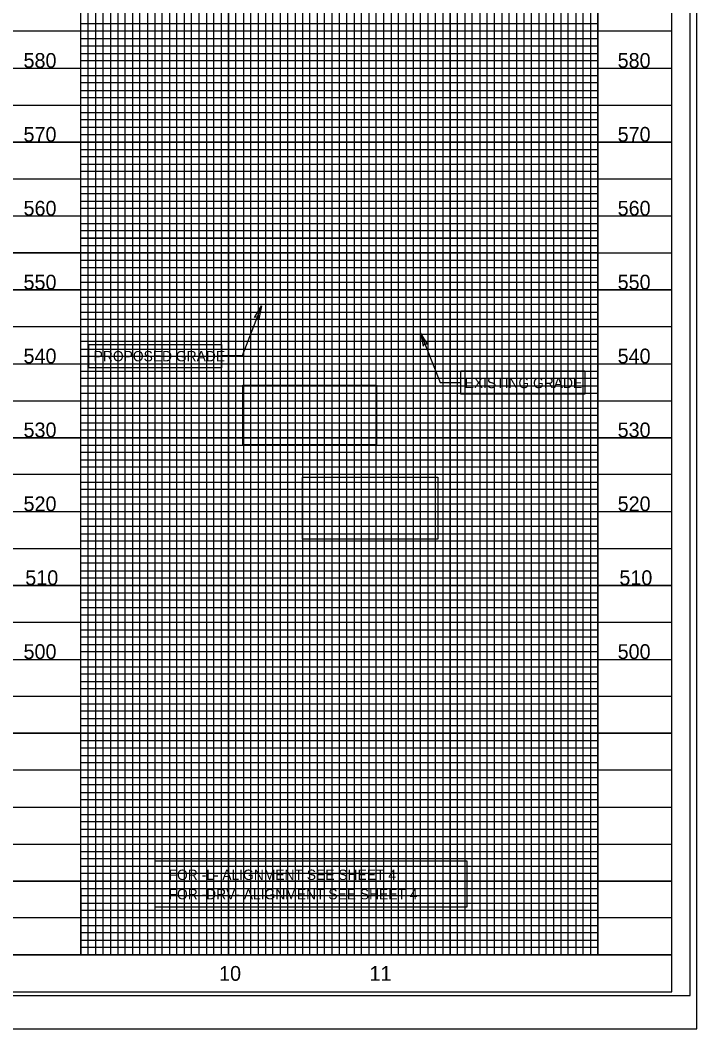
# Model space of a CAD drawing. Extents: x 1735444 to 1737729, y 696688 to 698970.
# Drawn here: x 1737271 to 1737729, y 697635 to 698318 of the extents above; entities that cross this region are included whole.
import ezdxf

# ---------------------------------------------------------------- set-up
doc = ezdxf.new("R2010")
doc.units = 0
for name, color, linetype in [('Exist Vertical Profile Horizontal Axis Label Major', 7, 'Continuous'), ('Exist Vertical Profile Vertical Axis Label', 7, 'Continuous'), ('Prop Grid Mask', 7, 'Continuous'), ('Prop PFL Text', 7, 'Continuous'), ('Prop Terminator CELL', 7, 'Continuous'), ('Prop VPI Label', 7, 'Continuous'), ('Sheet Cutting Line CELL', 7, 'Continuous'), ('Sheet DOT Grid CELL', 7, 'Continuous'), ('Sheet Layout Profile Border', 7, 'Continuous'), ('Sheet Plot Border Inside CELL', 7, 'Continuous'), ('Sheet Plot Border Outside CELL', 7, 'Continuous'), ('Sheet Profile CELL', 7, 'Continuous'), ('Sheet Profile Grid Major CELL', 7, 'Continuous'), ('Sheet Profile Grid Middle CELL', 7, 'Continuous'), ('Sheet Profile Grid Minor CELL', 7, 'Continuous')]:
    doc.layers.add(name, color=color, linetype=linetype)

msp = doc.modelspace()

# ---------------------------------------------------------------- linework, layer by layer
at = {"layer": 'Prop Grid Mask'}
for points in [[(1737317.56, 698098.19), (1737407.19, 698098.19), (1737407.19, 698082.43), (1737317.56, 698082.43)], [(1737569.28, 698080.28), (1737653.32, 698080.28), (1737653.32, 698064.52), (1737569.28, 698064.52)], [(1737421.76, 698070.57), (1737512.15, 698070.57), (1737512.15, 698030.37), (1737421.76, 698030.37)], [(1737462.19, 698008.39), (1737553.64, 698008.39), (1737553.64, 697966.39), (1737462.19, 697966.39)], [(1737573.49, 697748.56), (1737362.07, 697748.56), (1737362.07, 697717.68), (1737573.49, 697717.68)]]:
    msp.add_lwpolyline(points, close=True, dxfattribs=at)
at = {"layer": 'Prop Terminator CELL'}
for points in [[(1737429.69, 698116.5), (1737434.41, 698124.31), (1737432.6, 698115.3), (1737431.53, 698116.96)], [(1737546.78, 698098.36), (1737542.05, 698106.17), (1737543.86, 698097.16), (1737544.93, 698098.82)]]:
    msp.add_lwpolyline(points, close=True, dxfattribs=at)
at = {"layer": 'Prop VPI Label'}
for p, q in [((1737434.41, 698124.31), (1737421.19, 698090.55)), ((1737542.05, 698106.17), (1737555.28, 698072.4)), ((1737421.19, 698090.55), (1737407.19, 698090.55)), ((1737555.28, 698072.4), (1737569.28, 698072.4))]:
    msp.add_line(p, q, dxfattribs=at)
at = {"layer": 'Sheet Cutting Line CELL'}
msp.add_line((1736045.07, 697635.13), (1737729.07, 697635.13), dxfattribs=at)
at = {"layer": 'Sheet DOT Grid CELL'}
for p, q in [((1737362.07, 698710.13), (1737362.07, 697685.13)), ((1737412.07, 698617.69), (1737412.07, 697685.13)), ((1737462.07, 698617.69), (1737462.07, 697685.13)), ((1737512.07, 697685.13), (1737512.07, 698572.58)), ((1737562.07, 697685.13), (1737562.07, 698572.58)), ((1737612.07, 697685.13), (1737612.07, 698572.58)), ((1737662.07, 697685.13), (1737662.07, 698572.58)), ((1736212.07, 698285.13), (1737712.07, 698285.13)), ((1736212.07, 698235.13), (1737712.07, 698235.13)), ((1736212.07, 698185.13), (1737712.07, 698185.13)), ((1736212.07, 698135.13), (1737712.07, 698135.13)), ((1736212.07, 698085.13), (1737712.07, 698085.13)), ((1736212.07, 698035.13), (1737712.07, 698035.13)), ((1736212.07, 697985.13), (1737712.07, 697985.13)), ((1736212.07, 697935.13), (1737712.07, 697935.13)), ((1736212.07, 697885.13), (1737274.3, 697885.13)), ((1737274.3, 697885.13), (1737712.07, 697885.13)), ((1736212.07, 697835.13), (1737274.9, 697835.13)), ((1737274.9, 697835.13), (1737712.07, 697835.13)), ((1736212.07, 697785.13), (1737274.3, 697785.13)), ((1737274.3, 697785.13), (1737712.07, 697785.13)), ((1736212.07, 697735.13), (1737274.3, 697735.13)), ((1737274.3, 697735.13), (1737712.07, 697735.13)), ((1737312.07, 697730.13), (1737312.07, 697685.13))]:
    msp.add_line(p, q, dxfattribs=at)
at = {"layer": 'Sheet Layout Profile Border'}
msp.add_lwpolyline([(1737512.02, 698661.7), (1737512.02, 698710.13), (1736262.07, 698710.13), (1736262.07, 697685.13), (1737662.07, 697685.13), (1737662.07, 698572.58), (1737512.02, 698572.58), (1737512.02, 698617.69)], dxfattribs=at)
at = {"layer": 'Sheet Plot Border Inside CELL'}
msp.add_lwpolyline([(1737724.57, 698712.68), (1736058.07, 698712.68), (1736058.07, 697657.58), (1737724.57, 697657.58)], close=True, dxfattribs=at)
at = {"layer": 'Sheet Plot Border Outside CELL'}
msp.add_lwpolyline([(1737729.07, 698735.13), (1736045.07, 698735.13), (1736045.07, 697635.13), (1737729.07, 697635.13)], close=True, dxfattribs=at)
at = {"layer": 'Sheet Profile CELL'}
msp.add_line((1737712.07, 697685.13), (1736212.07, 697685.13), dxfattribs=at)
msp.add_lwpolyline([(1737712.07, 698710.13), (1736212.07, 698710.13), (1736212.07, 697660.13), (1737712.07, 697660.13)], close=True, dxfattribs=at)
at = {"layer": 'Sheet Profile Grid Major CELL'}
for points in [[(1736962.07, 697685.13), (1737012.07, 697685.13), (1737012.07, 698710.13), (1737062.07, 698710.13), (1737062.07, 697685.13), (1737112.07, 697685.13), (1737112.07, 698710.13), (1737162.07, 698710.13), (1737162.07, 697685.13), (1737212.07, 697685.13), (1737212.07, 698710.13), (1737262.07, 698710.13), (1737262.07, 697685.13), (1737312.07, 697685.13), (1737312.07, 698710.13), (1737362.07, 698710.13), (1737362.07, 697685.13), (1737412.07, 697685.13), (1737412.07, 698617.69)], [(1737462.07, 698617.69), (1737462.07, 697685.13), (1737512.07, 697685.13), (1737512.07, 698710.13), (1737538.37, 698710.13)], [(1737562.07, 698572.58), (1737562.07, 697685.13), (1737612.07, 697685.13), (1737612.07, 698572.58)], [(1737662.07, 698572.58), (1737662.07, 697685.13), (1737712.07, 697685.13)], [(1737712.07, 698235.13), (1736212.07, 698235.13), (1736212.07, 698285.13), (1737712.07, 698285.13)], [(1737712.07, 698135.13), (1736212.07, 698135.13), (1736212.07, 698185.13), (1737712.07, 698185.13)], [(1737712.07, 698035.13), (1736212.07, 698035.13), (1736212.07, 698085.13), (1737712.07, 698085.13)], [(1737712.07, 697935.13), (1736212.07, 697935.13), (1736212.07, 697985.13), (1737712.07, 697985.13)], [(1737712.07, 697835.13), (1736212.07, 697835.13), (1736212.07, 697885.13), (1737712.07, 697885.13)], [(1737712.07, 697735.13), (1736212.07, 697735.13), (1736212.07, 697785.13), (1737712.07, 697785.13)]]:
    msp.add_lwpolyline(points, dxfattribs=at)
at = {"layer": 'Sheet Profile Grid Middle CELL'}
for points in [[(1737312.07, 698710.13), (1737312.07, 698710.13), (1737337.07, 698710.13), (1737337.07, 697685.13), (1737387.07, 697685.13), (1737387.07, 698617.69)], [(1737437.07, 698617.69), (1737437.07, 697685.13), (1737487.07, 697685.13), (1737487.07, 698617.69)], [(1737537.07, 698572.58), (1737537.07, 697685.13), (1737587.07, 697685.13), (1737587.07, 698572.58)], [(1737637.07, 698572.58), (1737637.07, 697685.13)], [(1737712.07, 698310.13), (1736212.07, 698310.13), (1736212.07, 698260.13), (1737712.07, 698260.13)], [(1737712.07, 698210.13), (1736212.07, 698210.13), (1736212.07, 698160.13), (1737712.07, 698160.13)], [(1737712.07, 698110.13), (1736212.07, 698110.13), (1736212.07, 698060.13), (1737712.07, 698060.13)], [(1737712.07, 698010.13), (1736212.07, 698010.13), (1736212.07, 697960.13), (1737712.07, 697960.13)], [(1737275.01, 697910.13), (1736212.07, 697910.13), (1736212.07, 697860.13), (1737274.3, 697860.13)], [(1737712.07, 697910.13), (1737275.01, 697910.13)], [(1737274.3, 697860.13), (1737712.07, 697860.13)], [(1737274.9, 697810.13), (1736212.07, 697810.13), (1736212.07, 697760.13), (1737274.01, 697760.13)], [(1737712.07, 697810.13), (1737274.9, 697810.13)], [(1737274.01, 697760.13), (1737712.07, 697760.13)], [(1737712.07, 697710.13), (1736212.07, 697710.13)]]:
    msp.add_lwpolyline(points, dxfattribs=at)
at = {"layer": 'Sheet Profile Grid Minor CELL'}
for points in [[(1737307.07, 697685.13), (1737317.07, 697685.13), (1737317.07, 698710.13)], [(1737322.07, 698710.13), (1737322.07, 697685.13), (1737327.07, 697685.13), (1737327.07, 698710.13)], [(1737332.07, 698710.13), (1737332.07, 697685.13), (1737342.07, 697685.13), (1737342.07, 698710.13)], [(1737347.07, 698710.13), (1737347.07, 697685.13), (1737352.07, 697685.13), (1737352.07, 698710.13)], [(1737357.07, 698710.13), (1737357.07, 697685.13), (1737367.07, 697685.13), (1737367.07, 698710.13)], [(1737372.07, 698710.13), (1737372.07, 697685.13), (1737377.07, 697685.13), (1737377.07, 698710.13)], [(1737382.07, 698617.69), (1737382.07, 697685.13), (1737392.07, 697685.13), (1737392.07, 698617.69)], [(1737397.07, 698617.69), (1737397.07, 697685.13), (1737402.07, 697685.13), (1737402.07, 698617.69)], [(1737407.07, 698617.69), (1737407.07, 697685.13), (1737417.07, 697685.13), (1737417.07, 698617.69)], [(1737422.07, 698617.69), (1737422.07, 697685.13), (1737427.07, 697685.13), (1737427.07, 698617.69)], [(1737432.07, 698617.69), (1737432.07, 697685.13), (1737442.07, 697685.13), (1737442.07, 698617.69)], [(1737447.07, 698617.69), (1737447.07, 697685.13), (1737452.07, 697685.13), (1737452.07, 698617.69)], [(1737457.07, 698617.69), (1737457.07, 697685.13), (1737467.07, 697685.13), (1737467.07, 698617.69)], [(1737472.07, 698617.69), (1737472.07, 697685.13), (1737477.07, 697685.13), (1737477.07, 698617.69)], [(1737482.07, 698617.69), (1737482.07, 697685.13), (1737492.07, 697685.13), (1737492.07, 698617.69)], [(1737497.07, 698617.69), (1737497.07, 697685.13), (1737502.07, 697685.13), (1737502.07, 698617.69)], [(1737507.07, 698617.69), (1737507.07, 697685.13), (1737517.07, 697685.13), (1737517.07, 698572.58)], [(1737522.07, 698572.58), (1737522.07, 697685.13), (1737527.07, 697685.13), (1737527.07, 698572.58)], [(1737532.07, 698572.58), (1737532.07, 697685.13), (1737542.07, 697685.13), (1737542.07, 698572.58)], [(1737547.07, 698572.58), (1737547.07, 697685.13), (1737552.07, 697685.13), (1737552.07, 698572.58)], [(1737557.07, 698572.58), (1737557.07, 697685.13), (1737567.07, 697685.13), (1737567.07, 698572.58)], [(1737572.07, 698572.58), (1737572.07, 697685.13), (1737577.07, 697685.13), (1737577.07, 698572.58)], [(1737582.07, 698572.58), (1737582.07, 697685.13), (1737592.07, 697685.13), (1737592.07, 698572.58)], [(1737597.07, 698572.58), (1737597.07, 697685.13)], [(1737597.07, 697685.13), (1737602.07, 697685.13), (1737602.07, 698572.58)], [(1737607.07, 698572.58), (1737607.07, 697685.13), (1737617.07, 697685.13), (1737617.07, 698572.58)], [(1737622.07, 698572.58), (1737622.07, 697685.13), (1737627.07, 697685.13), (1737627.07, 698572.58)], [(1737632.07, 698572.58), (1737632.07, 697685.13), (1737642.07, 697685.13), (1737642.07, 698572.58)], [(1737647.07, 698572.58), (1737647.07, 697685.13), (1737652.07, 697685.13), (1737652.07, 698572.58)], [(1737657.07, 698572.58), (1737657.07, 697685.13), (1737667.07, 697685.13)], [(1737662.07, 698315.13), (1737312.07, 698315.13)], [(1737312.07, 698305.13), (1737662.07, 698305.13)], [(1737662.07, 698300.13), (1737312.07, 698300.13)], [(1737312.07, 698295.13), (1737662.07, 698295.13)], [(1737662.07, 698290.13), (1737312.07, 698290.13)], [(1737312.07, 698280.13), (1737662.07, 698280.13)], [(1737662.07, 698275.13), (1737312.07, 698275.13)], [(1737312.07, 698270.13), (1737662.07, 698270.13)], [(1737662.07, 698265.13), (1737312.07, 698265.13)], [(1737312.07, 698255.13), (1737662.07, 698255.13)], [(1737662.07, 698250.13), (1737312.07, 698250.13)], [(1737312.07, 698245.13), (1737662.07, 698245.13)], [(1737662.07, 698240.13), (1737312.07, 698240.13)], [(1737312.07, 698230.13), (1737662.07, 698230.13)], [(1737662.07, 698225.13), (1737312.07, 698225.13)], [(1737312.07, 698220.13), (1737662.07, 698220.13)], [(1737662.07, 698215.13), (1737312.07, 698215.13)], [(1737312.07, 698205.13), (1737662.07, 698205.13)], [(1737662.07, 698200.13), (1737312.07, 698200.13)], [(1737312.07, 698195.13), (1737662.07, 698195.13)], [(1737662.07, 698190.13), (1737312.07, 698190.13)], [(1737312.07, 698180.13), (1737662.07, 698180.13)], [(1737662.07, 698175.13), (1737312.07, 698175.13)], [(1737312.07, 698170.13), (1737662.07, 698170.13)], [(1737662.07, 698170.13), (1737312.07, 698170.13)], [(1737312.07, 698165.13), (1737662.07, 698165.13)], [(1737662.07, 698160.13), (1736262.07, 698160.13), (1736262.07, 698155.13), (1737262.07, 698155.13)], [(1737312.07, 698155.13), (1737662.07, 698155.13)], [(1737662.07, 698150.13), (1737312.07, 698150.13)], [(1737312.07, 698145.13), (1737662.07, 698145.13)], [(1737662.07, 698140.13), (1737312.07, 698140.13)], [(1737312.07, 698130.13), (1737662.07, 698130.13)], [(1737662.07, 698125.13), (1737312.07, 698125.13)], [(1737312.07, 698120.13), (1737662.07, 698120.13)], [(1737662.07, 698115.13), (1737312.07, 698115.13)], [(1737312.07, 698105.13), (1737662.07, 698105.13)], [(1737662.07, 698100.13), (1737312.07, 698100.13)], [(1737312.07, 698095.13), (1737662.07, 698095.13)], [(1737662.07, 698090.13), (1737312.07, 698090.13)], [(1737312.07, 698080.13), (1737662.07, 698080.13)], [(1737662.07, 698075.13), (1737312.07, 698075.13)], [(1737312.07, 698070.13), (1737662.07, 698070.13)], [(1737662.07, 698065.13), (1737312.07, 698065.13)], [(1737312.07, 698055.13), (1737662.07, 698055.13)], [(1737662.07, 698050.13), (1737312.07, 698050.13)], [(1737312.07, 698045.13), (1737662.07, 698045.13)], [(1737662.07, 698040.13), (1737312.07, 698040.13)], [(1737312.07, 698030.13), (1737662.07, 698030.13)], [(1737662.07, 698025.13), (1737312.07, 698025.13)], [(1737312.07, 698020.13), (1737662.07, 698020.13)], [(1737662.07, 698015.13), (1737312.07, 698015.13)], [(1737312.07, 698005.13), (1737662.07, 698005.13)], [(1737662.07, 698000.13), (1737312.07, 698000.13)], [(1737312.07, 697995.13), (1737662.07, 697995.13)], [(1737662.07, 697990.13), (1737312.07, 697990.13)], [(1737312.07, 697980.13), (1737662.07, 697980.13)], [(1737662.07, 697975.13), (1737312.07, 697975.13)], [(1737312.07, 697970.13), (1737662.07, 697970.13)], [(1737662.07, 697965.13), (1737312.07, 697965.13)], [(1737312.07, 697955.13), (1737662.07, 697955.13)], [(1737662.07, 697950.13), (1737312.07, 697950.13)], [(1737312.07, 697945.13), (1737662.07, 697945.13)], [(1737662.07, 697940.13), (1737312.07, 697940.13)], [(1737312.07, 697930.13), (1737662.07, 697930.13)], [(1737662.07, 697925.13), (1737312.07, 697925.13)], [(1737312.07, 697920.13), (1737662.07, 697920.13)], [(1737662.07, 697915.13), (1737312.07, 697915.13)], [(1737312.07, 697905.13), (1737662.07, 697905.13)], [(1737662.07, 697900.13), (1737312.07, 697900.13)], [(1737312.07, 697895.13), (1737662.07, 697895.13)], [(1737662.07, 697890.13), (1737312.07, 697890.13)], [(1737312.07, 697880.13), (1737662.07, 697880.13)], [(1737662.07, 697875.13), (1737312.07, 697875.13)], [(1737312.07, 697870.13), (1737662.07, 697870.13)], [(1737662.07, 697865.13), (1737312.07, 697865.13)], [(1737312.07, 697855.13), (1737662.07, 697855.13)], [(1737662.07, 697850.13), (1737312.07, 697850.13)], [(1737312.07, 697845.13), (1737662.07, 697845.13)], [(1737662.07, 697840.13), (1737312.07, 697840.13)], [(1737312.07, 697830.13), (1737662.07, 697830.13)], [(1737662.07, 697825.13), (1737312.07, 697825.13)], [(1737312.07, 697820.13), (1737662.07, 697820.13)], [(1737662.07, 697815.13), (1737312.07, 697815.13)], [(1737312.07, 697805.13), (1737662.07, 697805.13)], [(1737662.07, 697800.13), (1737312.07, 697800.13)], [(1737312.07, 697795.13), (1737662.07, 697795.13)], [(1737662.07, 697790.13), (1737312.07, 697790.13)], [(1737312.07, 697780.13), (1737662.07, 697780.13)], [(1737662.07, 697775.13), (1737312.07, 697775.13)], [(1737312.07, 697770.13), (1737662.07, 697770.13)], [(1737662.07, 697765.13), (1737312.07, 697765.13)], [(1737312.07, 697755.13), (1737662.07, 697755.13)], [(1737662.07, 697750.13), (1737312.07, 697750.13)], [(1737312.07, 697745.13), (1737662.07, 697745.13)], [(1737662.07, 697740.13), (1737312.07, 697740.13)], [(1737312.07, 697730.13), (1737662.07, 697730.13)], [(1737662.07, 697725.13), (1737312.07, 697725.13)], [(1737312.07, 697720.13), (1737662.07, 697720.13)], [(1737662.07, 697715.13), (1737312.07, 697715.13)], [(1737312.07, 697705.13), (1737662.07, 697705.13)], [(1737662.07, 697700.13), (1737312.07, 697700.13)], [(1737312.07, 697695.13), (1737662.07, 697695.13)], [(1737662.07, 697690.13), (1737312.07, 697690.13)]]:
    msp.add_lwpolyline(points, dxfattribs=at)

# ---------------------------------------------------------------- texts
at = {"layer": 'Exist Vertical Profile Horizontal Axis Label Major'}
for s, p in [('10', (1737405.64, 697667.63)), ('11', (1737507.48, 697667.63))]:
    msp.add_text(s, height=10, dxfattribs=at).set_placement(p)
at = {"layer": 'Exist Vertical Profile Vertical Axis Label'}
for s, p in [('580', (1737273.25, 698285.38)), ('580', (1737675.45, 698285.38)), ('570', (1737273.25, 698235.38)), ('570', (1737675.45, 698235.38)), ('560', (1737273.25, 698185.38)), ('560', (1737675.45, 698185.38)), ('550', (1737273.25, 698135.38)), ('550', (1737675.45, 698135.38)), ('540', (1737273.25, 698085.38)), ('540', (1737675.45, 698085.38)), ('530', (1737273.25, 698035.38)), ('530', (1737675.45, 698035.38)), ('520', (1737273.25, 697985.38)), ('520', (1737675.45, 697985.38)), ('510', (1737274.44, 697935.38)), ('510', (1737676.64, 697935.38)), ('500', (1737273.25, 697885.38)), ('500', (1737675.45, 697885.38))]:
    msp.add_text(s, height=10, dxfattribs=at).set_placement(p)
at = {"layer": 'Prop PFL Text'}
for s, p in [('PROPOSED GRADE', (1737320.74, 698086.78)), ('EXISTING GRADE', (1737571.89, 698068.64)), ('FOR -L- ALIGNMENT SEE SHEET 4', (1737371.42, 697735.86)), ('FOR -DRV- ALIGNMENT SEE SHEET 4', (1737371.42, 697722.74))]:
    msp.add_text(s, height=7, dxfattribs=at).set_placement(p)

doc.saveas('drawing.dxf')
